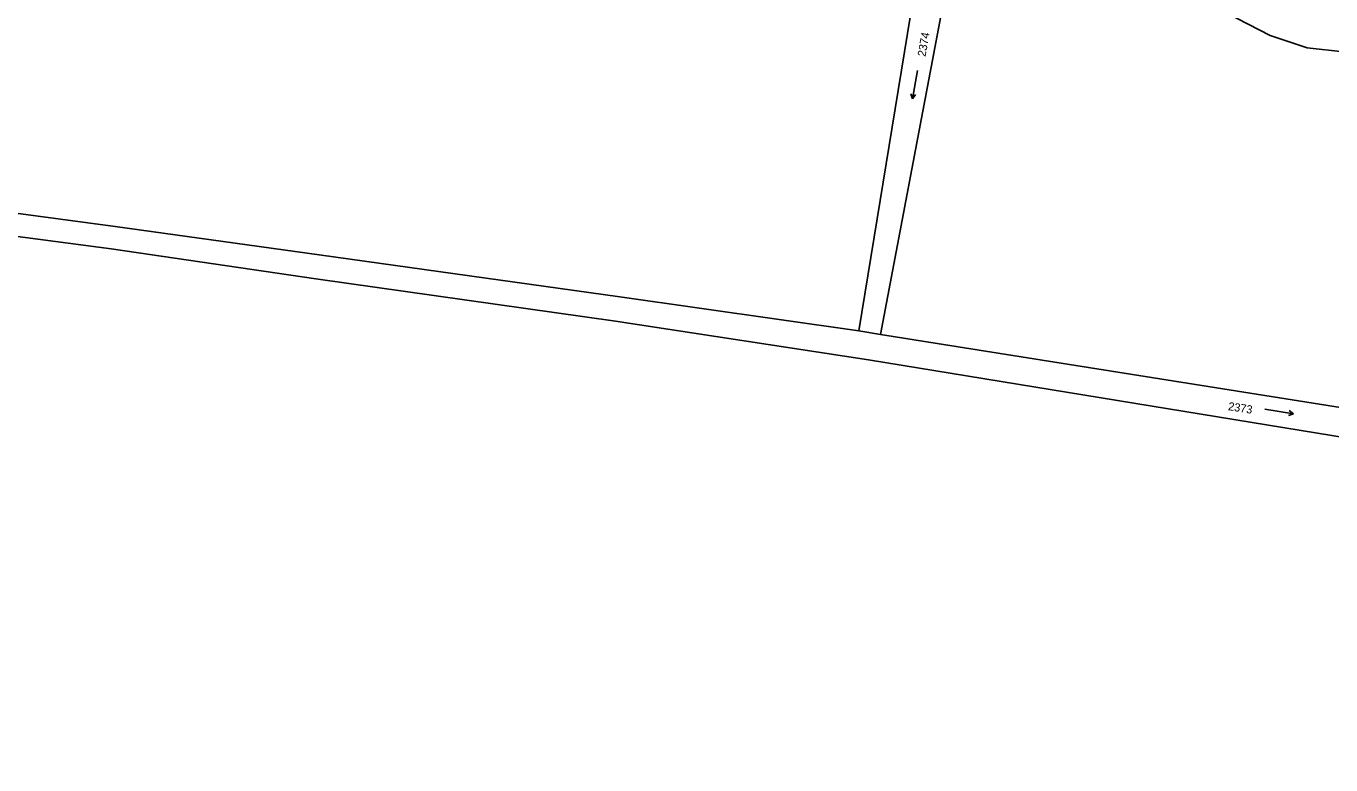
# Model space of a CAD drawing. Extents: x -504988 to -494607, y -1123820 to -1114018.
# Drawn here: x -500642.7 to -500371.7, y -1121310 to -1121156.5 of the extents above; entities that cross this region are included whole.
import ezdxf

# ---------------------------------------------------------------- set-up
doc = ezdxf.new("R2010")
doc.units = 0
for name, color, linetype in [('Hranice parcel', 7, 'Continuous'), ('Parcelní čísla', 7, 'Continuous'), ('Značky kultur', 7, 'Continuous')]:
    doc.layers.add(name, color=color, linetype=linetype)

msp = doc.modelspace()

# ---------------------------------------------------------------- linework, layer by layer
at = {"layer": 'Hranice parcel'}
for p, q in [((-500469.81, -1121219.81), (-500453.45, -1121120.1)), ((-500446.85, -1121123.24), (-500465.32, -1121220.56)), ((-500465.32, -1121220.56), (-500469.81, -1121219.81))]:
    msp.add_line(p, q, dxfattribs=at)
for points in [[(-500093.53, -1121309.79), (-500096.64, -1121297.58), (-500125.14, -1121250.31), (-500143.37, -1121221.49), (-500154.49, -1121207.58), (-500171.25, -1121193.24), (-500179.79, -1121189.25), (-500191.69, -1121184.83), (-500210.15, -1121179.42), (-500240.92, -1121170.5), (-500265.19, -1121164.1), (-500289.32, -1121158.74), (-500305.17, -1121156.16), (-500321.82, -1121158.18), (-500359.14, -1121160.88), (-500369.12, -1121161.84), (-500376.67, -1121161), (-500384.33, -1121158.44), (-500393.5, -1121153.73), (-500419.45, -1121136.05), (-500446.85, -1121123.24)], [(-500689.12, -1121188.67), (-500657.34, -1121193.71), (-500624.21, -1121198.12), (-500581.87, -1121204.05), (-500519.39, -1121212.76), (-500469.81, -1121219.81)], [(-500099.19, -1121315.37), (-500113.09, -1121309.98), (-500184.11, -1121290.7), (-500248.64, -1121271.81), (-500285.69, -1121261.64), (-500326.32, -1121249.51), (-500340.18, -1121246.71), (-500467.78, -1121225.87), (-500520.34, -1121217.8), (-500582.53, -1121209), (-500625.06, -1121202.79), (-500658.2, -1121198.42), (-500690.57, -1121193.22)], [(-500465.32, -1121220.56), (-500339.23, -1121240.59), (-500324.95, -1121243.16), (-500283.43, -1121254.1), (-500246.86, -1121265.89), (-500182.29, -1121284.98), (-500111.77, -1121304.75), (-500093.53, -1121309.79)]]:
    msp.add_lwpolyline(points, dxfattribs=at)
at = {"layer": 'Značky kultur'}
for p, q in [((-500457.63, -1121165.72), (-500458.67, -1121171.63)), ((-500458.67, -1121171.63), (-500459, -1121170.58)), ((-500458.67, -1121171.63), (-500458.01, -1121170.76)), ((-500385.45, -1121236.1), (-500379.52, -1121237.04)), ((-500379.52, -1121237.04), (-500380.57, -1121237.38)), ((-500379.52, -1121237.04), (-500380.41, -1121236.39))]:
    msp.add_line(p, q, dxfattribs=at)

# ---------------------------------------------------------------- texts
at = {"layer": 'Parcelní čísla'}
for s, rotation, p in [('2374', 80, (-500455.95, -1121162.95)), ('2373', 351, (-500393.18, -1121236.28))]:
    msp.add_text(s, height=1.7, rotation=rotation, dxfattribs=at).set_placement(p)

doc.saveas('drawing.dxf')
